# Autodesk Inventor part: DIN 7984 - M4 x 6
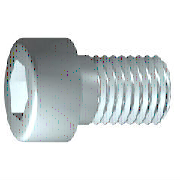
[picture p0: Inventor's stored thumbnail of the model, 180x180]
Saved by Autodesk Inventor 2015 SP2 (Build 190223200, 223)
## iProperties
IsCustomPart: 0
Created: 2012-02
Part Number: DIN 7984 - M4 x 6
Material: Steel, Mild
Description: Cylinder Head Cap Screw
Document SubType Name: Modeling
Standard: DIN 7984
Designer: rYan
Standard Revision: 1985
Standards Organization: DIN
Language: en-US
Size Designation: M4 x 6
Categories: <MemberInstance><Categories><Category DisplayName="Fasteners" InternalName="e4da775c-781d-43d5-af7c-5136215cf5a6" Mnemonic="FSTN"><Category DisplayName="Bolts"
Density: 7.85 g/cm^3
Mass: 1.31215 g
Surface Area: 2.27551 cm^2
Volume: 0.167153 cm^3
Appearance: Halbpoliert
Author: rYan
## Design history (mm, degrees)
sketch "Sketch1"
  geometry: L1 (0.333, 0)-(6, 0); L2 (6, 0)-(6, 2); L3 (6, 2)-(2.1, 2); L4 (2.1, 2)-(1.67, 2); L5 (1.67, 2)-(0, 2); L6 (0, 2)-(0, 3.5); L7 (0, 3.5)-(-2.8, 3.5); L8 (-2.8, 3.5)-(-2.8, 1.443); L9 (-2.8, 1.443)-(-0.5, 1.443); L10 (-0.5, 1.443)-(0.333, 0); L11 (-4.56, 0)-(7.76, 0) reference; L12 (0, -0.7)-(0, 4.2) reference; L13 (2.1, 2)-(0, 2)
  constraints: 22 end point, 6 parallel, 2 collinear, 2 perpendicular, 1 horizontal, 1 point on line
  dimensions: "d1" = 3.9 distance from line of L3.end L2 (= GEL); "d2" = 0.42952 distance of L4.end L3.end (computed from GAL); "d3" = 2.8 distance between parallel lines of L8 L6 (= KOH); "d4" = 2.3 distance of L8.end L9.end (= INTI); "d5" = 60 deg angle of L10 L1; "d6" = 4 diameter of L3 L1 (= GD); "d7" = 4 diameter of L5 L1 (= BDM); "d8" = 2.88675 diameter of L9 L1 (= 1.1547 x SW); "d9" = 7 diameter of L7 L1 (= KOD); "d26" = 6 distance between parallel lines of L12 L2 (= NLG)
revolve "Body" sketch "Sketch1" stored, may be unused: angle "d10" = 90 deg
sketch "Sketch2"
  geometry: L1 (0, -4.9)-(0, 4.9) reference; L2 (-4.9, 0)-(4.9, 0) reference; L3 (1.443, 0)-(0.722, -1.25); L4 (0.722, -1.25)-(-0.722, -1.25); L5 (-0.722, -1.25)-(-1.443, 0); L6 (-1.443, 0)-(-0.722, 1.25); L7 (-0.722, 1.25)-(0.722, 1.25); L8 (0.722, 1.25)-(1.443, 0); 2 further points
  constraints: 12 end point, 1 coincident, 1 horizontal alignment, 1 point on line, 12 other
extrude "Slot" join sketch "Sketch2" stored distance "d11" = 10; taper "d12" = 0 deg
fillet "Fillet1" dims "d17" = 0.4 (= RR)
feature "Thread" dims "d13" = 3.9 (= GEL), "d14" = 0
chamfer "Chamfer1" distance "d15" = 0.42941 (= -0.5 x SPD + 0.5 x GD); stored, may be unused: second distance "d16" = 0.42941 (= GUL), angle "d27" = 45 deg
workplane "Work Plane1"
fillet "Fillet2" dims "d30" = 0.1 (= R)
body "Solid1"
other parameters: "GD" = 4 (= NND) [user parameter; used in 2 equation terms], "NLG" = 6 [user parameter; used in 1 equation term], "GEL" = 3.9 [user parameter; used in 2 equation terms], "KOD" = 7 [user parameter; used in 1 equation term], "KOH" = 2.8 [user parameter; used in 1 equation term], "INTI" = 2.3 [user parameter; used in 1 equation term], "GAL" = 0.42941 (= 0.61345 x PTC) [user parameter; used in 1 equation term], "GUL" = 0.42941 (= 0.61345 x PTC) [user parameter; used in 1 equation term], "BDM" = 4 (= NND) [user parameter; used in 1 equation term], "SW" = 2.5 [user parameter; used in 2 equation terms], "RR" = 0.4 [user parameter; used in 1 equation term], "SPD" = 3.14117 (= NND - 1.2269 x PTC) [user parameter; used in 1 equation term], "d19" = 0, "d28" = 0, "d29" = 0, "R" = 0.1 [user parameter; used in 1 equation term], "TOA" = 30 deg [user parameter], "GD1" = 3.14117 (= THREADDIA - 1.2269 x PTC) [user parameter], "THREADDIA" = 4 [user parameter; used in 1 equation term], "FAWI" = 45 deg [user parameter], "ANG" = 120 deg [user parameter], "TPU" = 14.28571 (computed from PTC) [user parameter], "PTC" = 0.7 [user parameter; used in 5 equation terms], "NND" = 4 [user parameter; used in 3 equation terms], "E0" = 2.8875 (= 1.155 x SW) [user parameter]
